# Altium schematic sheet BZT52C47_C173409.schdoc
size 127 x 101 mm
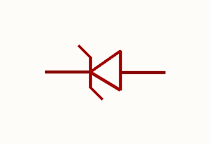
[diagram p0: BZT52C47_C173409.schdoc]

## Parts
D?  bzt52c47_c173409  [SOD-123_L2.8-W1.8-LS3.7-RD]  (value not drawn)

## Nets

Not connected (* = marked no-connect by the designer): D? 1 2

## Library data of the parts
D? = bzt52c47_c173409: 二极管配置:1个独立式;稳压值(标称值):47V;稳压值(范围):44.65V~49.35V;耗散功率(Pd):500mW;; Manufacturer: MDD(辰达半导体); AddInBom: yes; ModelId: 7884390a25fb4c08947731ebfba7e3f8; ModelTransform: 144.8816,62.992,0,0,0,0,0,0,0; Diode Configuration: 1个独立式; Zener Voltage(Nom): 47V; Reverse Leakage Current (Ir): 2uA@36V; Pd - Power Dissipation: 500mW; Impedance(Zzt): 150Ω; Tolerance: ±5%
